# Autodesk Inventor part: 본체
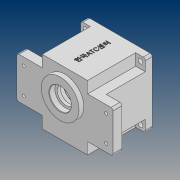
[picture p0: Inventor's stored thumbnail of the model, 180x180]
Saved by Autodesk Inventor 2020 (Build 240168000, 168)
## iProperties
Created: 2020-07
Part Number: 본체
Material: 일반
Document SubType Name: Modeling
Designer: PC312-
Density: 1 g/cm^3
Appearance: 기본값
Author: PC312-
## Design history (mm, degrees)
sketch "스케치1"
  geometry: L1 (0, 0)-(0, 94); L2 (0, 94)-(-33, 94); L3 (-33, 94)-(-33, 77); L4 (-33, 77)-(-70, 77); L5 (-70, 77)-(-70, 17); L6 (-70, 17)-(-33, 17); L7 (-33, 17)-(-33, 0); L8 (-33, 0)-(0, 0); L9 (0, 94)-(33, 94); L10 (33, 94)-(33, 77); L11 (33, 77)-(70, 77); L12 (70, 77)-(70, 17); L13 (70, 17)-(33, 17); L14 (33, 17)-(33, 0); L15 (33, 0)-(0, 0); L16 (-84.809, 47)-(80.616, 47)
  constraints: 32 end point, 6 symmetric about line, 5 horizontal, 4 point on line, 3 vertical
  dimensions: "d0" = 94 distance of L1.start L1.end; "d1" = 140 distance between parallel lines of L12 L5; "d2" = 60 distance between parallel lines of L13 L11; "d3" = 47 distance between parallel lines of L15 L16; "d4" = 33 distance between parallel lines of L1 L3; "d5" = 30 distance between parallel lines of L16 L4
extrude "돌출1" new body sketch "스케치1" distance "d6" = 13; taper "d7" = 0 deg
node "작업 평면1"
sketch "스케치3"
  geometry: L1 (-47, 0)-(47, 0); L2 (47, 0)-(47, 94); L3 (47, 94)-(-47, 94); L4 (-47, 94)-(-47, 0); L5 (-47, 0)-(47, 94); L6 (47, 0)-(-47, 94); 3 further points
  constraints: 12 end point, 3 midpoint, 2 parallel, 1 coincident, 1 horizontal, 1 perpendicular
  dimensions: "d11" = 94 distance of L2.end L3.end; "d12" = 94 distance of L1.end L2.end
extrude "돌출2" join sketch "스케치3" distance "d13" = 10; taper "d14" = 0 deg
sketch "스케치4"
  geometry: L1 (-47, 0)-(-47, 94) reference; L2 (47, 94)-(47, 0) reference; L3 (-70, 77)-(-33, 77) reference; L4 (-33, 77)-(-33, 94) reference; L5 (-33, 94)-(33, 94) reference; L6 (33, 94)-(33, 77) reference; L7 (33, 77)-(70, 77) reference; L8 (70, 17)-(33, 17) reference; L9 (33, 17)-(33, 0) reference; L10 (-33, 17)-(-70, 17) reference; L11 (-33, 0)-(-33, 17) reference; L12 (33, 0)-(-33, 0) reference; 5 further points
extrude "돌출3" join sketch "스케치4" stored distance "d15" = 10; taper "d16" = 0 deg
sketch "스케치5"
  geometry: L1 (-33, 0)-(33, 0) reference; L2 (33, 17)-(70, 17) reference; C1 r 27.5 at (0, 58); 2 further points
  constraints: 1 centre point, 1 midpoint, 1 vertical alignment
  dimensions: "d17" = 55 diameter of C1; "d18" = 41 distance from line of C1.centre L2
extrude "돌출4" join sketch "스케치5" distance "d19" = 7; taper "d20" = 0 deg
sketch "스케치6"
  geometry: L1 (47, 0)-(-47, 0) reference; C1 r 43 at (0, 47); 2 further points
  constraints: 1 centre point, 1 midpoint, 1 vertical alignment
  dimensions: "d21" = 86 diameter of C1; "d22" = 47 distance of C1.centre point (0, 0)
extrude "돌출5" cut sketch "스케치6" distance "d23" = 9; taper "d24" = 0 deg
sketch "스케치7"
  geometry: C1 r 43 at (0, 0) reference; C2 r 40 at (0, 0); 1 further point
  constraints: 1 centre point, 1 coincident
  dimensions: "d25" = 80 diameter of C2
extrude "돌출6" cut sketch "스케치7" distance "d26" = 62; taper "d27" = 0 deg
sketch "스케치8"
  geometry: C1 r 43 at (0, 0) reference; A1 r 21 centre (0, 11) between (8.978, -7.984) and (-8.978, -7.984); A2 r 15 centre (0, -20) between (-8.978, -7.984) and (8.978, -7.984); 1 further point
  constraints: 4 point on circle, 2 centre point, 2 vertical alignment
  dimensions: "d28" = 11 distance of A1.centre C1.centre; "d29" = 42 diameter of A1; "d30" = 30 diameter of A2; "d31" = 20 distance of A2.centre C1.centre
extrude "돌출7" join sketch "스케치8" distance "d32" = 7; taper "d33" = 0 deg
sketch "스케치9"
  geometry: L1 (47, 30.341)-(47, -74.969); L2 (0, -57)-(0, 13) reference; L3 (58, 30.341)-(58, -74.969); L4 (85.5, 20)-(30.5, 20) reference; L5 (74, 20)-(74, 11.7); L6 (74, 11.7)-(70.5, 11.7); L7 (70.5, 11.7)-(70.5, 7); L8 (70.5, 7)-(75.5, 7); L9 (75.5, 7)-(75.5, -3); L10 (39.016, -3)-(79, -3) reference; L11 (74, 20)-(58, 20); L12 (75.5, -3)-(58, -3); 2 further points
  constraints: 18 end point, 4 point on line, 4 vertical, 2 horizontal, 1 midpoint, 1 parallel
  dimensions: "d34" = 47 distance between parallel lines of L1 L2; "d35" = 11 distance between parallel lines of L1 L3; "d36" = 32 diameter of L5 L3; "d37" = 25 diameter of L7 L3; "d38" = 35 diameter of L9 L3; "d39" = 8.3 distance between parallel lines of L4 L6; "d40" = 10 distance between parallel lines of L10 L8
revolve "회전1" sketch "스케치9" stored, may be unused: angle "d41" = 90 deg
sketch "스케치10"
  geometry: L1 (27, 23.438)-(27, -84.761); L2 (47, 29.056)-(47, -82.353); L3 (0, -57)-(0, 13) reference; L4 (27, 7)-(36.5, 7); L5 (36.5, 7)-(36.5, 4); L6 (36.5, 4)-(38, 4); L7 (38, 4)-(38, -3); L8 (38, -3)-(27, -3); L9 (12, -3)-(39.016, -3) reference; 1 further point
  constraints: 14 end point, 4 point on line, 4 vertical, 2 horizontal
  dimensions: "d42" = 47 distance between parallel lines of L2 L3; "d43" = 20 distance between parallel lines of L1 L2; "d44" = 3 distance between parallel lines of L6 L4; "d45" = 7 distance between parallel lines of L8 L6; "d46" = 19 diameter of L5 L1; "d47" = 22 diameter of L7 L1
revolve "회전2" sketch "스케치10" stored, may be unused: angle "d48" = 90 deg
sketch "스케치11"
  geometry: C1 r 43 at (0, 0) reference; A1 r 40 centre (0, 0) between (-39.279, 7.559) and (-39.279, -7.559) reference; A2 r 36 centre (0, 0) between (-36, 0) and (-35.772, 4.045); A3 r 4 centre (-36, 0) between (-36.19, -3.995) and (-36.19, 3.995); A4 r 3 centre (-36.333, 6.992) between (-39.279, 7.559) and (-35.772, 4.045); A5 r 3 centre (-36.333, -6.992) between (-35.772, -4.045) and (-39.279, -7.559); 1 further point
  constraints: 13 point on circle, 4 centre point, 4 tangent, 1 coincident, 1 horizontal alignment
  dimensions: "d49" = 72 diameter of A2; "d50" = 8 diameter of A3; "d51" = 6 diameter of A4; "d52" = 6 diameter of A5
extrude "돌출8" join sketch "스케치11" distance "d53" = 62; taper "d54" = 0 deg
sketch "스케치12"
  geometry: L1 (-70, 77)-(-33, 77) reference; 3 further points
  constraints: 1 vertical alignment
  dimensions: "d62" = 60 horizontal distance of point (-60, 66) point (0, 0); "d63" = 11 distance from line of point (-60, 66) L1; "d64" = 38 distance of point (-60, 28) point (-60, 66)
hole "구멍1" sketch "스케치12" at (-60, 66), (-60, 28) diameter "d55" = 4.5; stored, may be unused: countersink angle "d59" = 90 deg, drill point angle "d61" = 118 deg; dims "d56" = 6, "d57" = 10, "d58" = 5, "d60" = 8
sketch "스케치13"
  geometry: L1 (-47, 94)-(47, 94) reference; L2 (47, 0)-(-47, 0) reference; 3 further points
  constraints: 1 vertical alignment
  dimensions: "d72" = 40 horizontal distance of point (-40, 87) point (0, 0); "d73" = 7 distance from line of point (-40, 87) L1; "d74" = 7 distance from line of point (-40, 7) L2
hole "구멍2" sketch "스케치13" at (-40, 87), (-40, 7) diameter "d65" = 7; stored, may be unused: countersink angle "d69" = 90 deg, drill point angle "d71" = 118 deg; dims "d66" = 6, "d67" = 10, "d68" = 5, "d70" = 8
sketch "스케치14"
  geometry: L1 (47, -47)-(-47, -47) reference; C1 r 43 at (0, 0) reference; C2 r 27.5 at (0, 11) reference; 2 further points
  dimensions: "d82" = 47 distance from line of point (-36, 0) L1; "d83" = 36 horizontal distance of C2.centre point (-36, 0)
hole "구멍3" sketch "스케치14" at (-36, 0) diameter "d75" = 3.242; stored, may be unused: countersink angle "d79" = 90 deg, drill point angle "d81" = 118 deg; dims "d76" = 7, "d77" = 10, "d78" = 5, "d80" = 9
chamfer "모따기1" distance "d84" = 0.8; stored, may be unused: second distance "d85" = 2, angle "d86" = 30 deg
fillet "모깎기1" dims "d87" = 3
chamfer "모따기2" distance "d88" = 1; stored, may be unused: second distance "d89" = 2, angle "d90" = 30 deg
chamfer "모따기3" distance "d91" = 1; stored, may be unused: second distance "d92" = 2, angle "d93" = 30 deg
chamfer "모따기4" distance "d94" = 1; stored, may be unused: second distance "d95" = 2, angle "d96" = 30 deg
fillet "모깎기2" dims "d97" = 3
fillet "모깎기3" dims "d98" = 3
node "작업 평면2"
sketch "스케치15"
  geometry: L1 (77, 80)-(-11, 80) reference; 2 further points
  constraints: 1 vertical alignment, 1 other
  dimensions: "d100" = 40 distance from line of L1 point (33, 40)
feature "엠보싱1" sketch "스케치15" dims "d0" = 94, "d1" = 140, "d2" = 60, "d3" = 47, "d4" = 33, "d5" = 30, "d11" = 94, "d12" = 94, "d101" = 0.5, "d102" = 0
node "솔리드1"
mirror "미러1"
mirror "미러2"
mirror "미러3"
mirror "미러4"
feature "A9D066F2-1C7D-4E18-AEED-F7BC21143FA4" dims "d55" = 4.5, "d56" = 6, "d57" = 10, "d58" = 5, "d59" = 90 deg, "d60" = 8, "d61" = 118 deg
